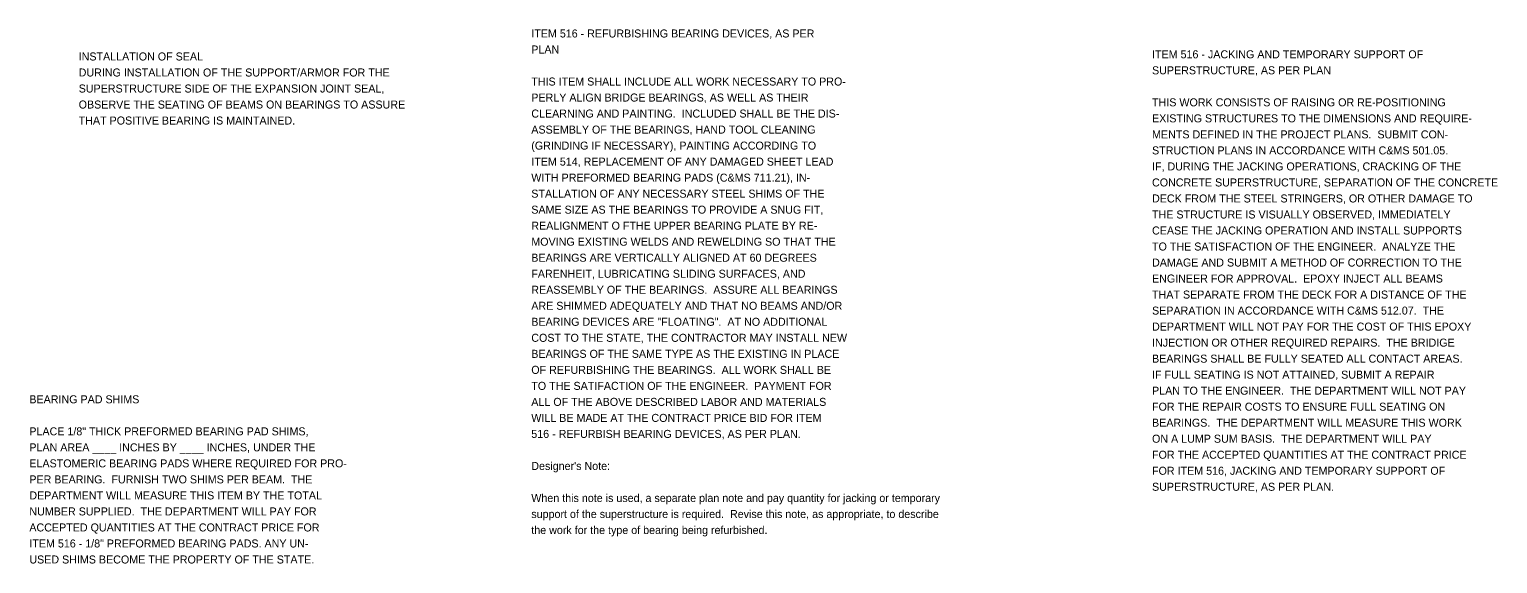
# Model space of a CAD drawing. Extents: x -11.4 to 50.8, y -16 to 31.7.
# Drawn here: x 25.08 to 50.76, y -14.14 to -4.8 of the extents above; entities that cross this region are included whole.
import ezdxf

# ---------------------------------------------------------------- set-up
doc = ezdxf.new("R2010")
doc.units = 0
doc.layers.add('SH_Text', color=7, linetype='Continuous')

msp = doc.modelspace()

# ---------------------------------------------------------------- texts
at = {"layer": 'SH_Text'}
for s, p in [('ITEM 516 - REFURBISHING BEARING DEVICES, AS PER', (33.857, -4.943)), ('PLAN', (33.857, -5.223)), ('INSTALLATION OF SEAL', (25.94, -5.345)), ('ITEM 516 - JACKING AND TEMPORARY SUPPORT OF', (44.715, -5.307)), ('DURING INSTALLATION OF THE SUPPORT/ARMOR FOR THE', (25.94, -5.625)), ('THIS ITEM SHALL INCLUDE ALL WORK NECESSARY TO PRO-', (33.857, -5.783)), ('SUPERSTRUCTURE, AS PER PLAN', (44.715, -5.587)), ('SUPERSTRUCTURE SIDE OF THE EXPANSION JOINT SEAL,', (25.94, -5.905)), ('OBSERVE THE SEATING OF BEAMS ON BEARINGS TO ASSURE', (25.94, -6.185)), ('PERLY ALIGN BRIDGE BEARINGS, AS WELL AS THEIR', (33.857, -6.063)), ('THIS WORK CONSISTS OF RAISING OR RE-POSITIONING', (44.715, -6.147)), ('THAT POSITIVE BEARING IS MAINTAINED.', (25.94, -6.465)), ('CLEARNING AND PAINTING.  INCLUDED SHALL BE THE DIS-', (33.857, -6.343)), ('EXISTING STRUCTURES TO THE DIMENSIONS AND REQUIRE-', (44.715, -6.427)), ('ASSEMBLY OF THE BEARINGS, HAND TOOL CLEANING', (33.857, -6.623)), ('MENTS DEFINED IN THE PROJECT PLANS.  SUBMIT CON-', (44.715, -6.707)), ('(GRINDING IF NECESSARY), PAINTING ACCORDING TO', (33.857, -6.903)), ('STRUCTION PLANS IN ACCORDANCE WITH C&MS 501.05.', (44.715, -6.987)), ('ITEM 514, REPLACEMENT OF ANY DAMAGED SHEET LEAD', (33.857, -7.183)), ('IF, DURING THE JACKING OPERATIONS, CRACKING OF THE', (44.715, -7.267)), ('WITH PREFORMED BEARING PADS (C&MS 711.21), IN-', (33.857, -7.463)), ('CONCRETE SUPERSTRUCTURE, SEPARATION OF THE CONCRETE', (44.715, -7.547)), ('STALLATION OF ANY NECESSARY STEEL SHIMS OF THE', (33.857, -7.743)), ('DECK FROM THE STEEL STRINGERS, OR OTHER DAMAGE TO', (44.715, -7.827)), ('SAME SIZE AS THE BEARINGS TO PROVIDE A SNUG FIT,', (33.857, -8.023)), ('REALIGNMENT O FTHE UPPER BEARING PLATE BY RE-', (33.857, -8.303)), ('THE STRUCTURE IS VISUALLY OBSERVED, IMMEDIATELY', (44.715, -8.107)), ('MOVING EXISTING WELDS AND REWELDING SO THAT THE', (33.857, -8.583)), ('CEASE THE JACKING OPERATION AND INSTALL SUPPORTS', (44.715, -8.387)), ('BEARINGS ARE VERTICALLY ALIGNED AT 60 DEGREES', (33.857, -8.863)), ('TO THE SATISFACTION OF THE ENGINEER.  ANALYZE THE', (44.715, -8.667)), ('DAMAGE AND SUBMIT A METHOD OF CORRECTION TO THE', (44.715, -8.947)), ('FARENHEIT, LUBRICATING SLIDING SURFACES, AND', (33.857, -9.143)), ('ENGINEER FOR APPROVAL.  EPOXY INJECT ALL BEAMS', (44.715, -9.227)), ('REASSEMBLY OF THE BEARINGS.  ASSURE ALL BEARINGS', (33.857, -9.423)), ('THAT SEPARATE FROM THE DECK FOR A DISTANCE OF THE', (44.715, -9.507)), ('ARE SHIMMED ADEQUATELY AND THAT NO BEAMS AND/OR', (33.857, -9.703)), ('SEPARATION IN ACCORDANCE WITH C&MS 512.07.  THE', (44.715, -9.787)), ('BEARING DEVICES ARE "FLOATING".  AT NO ADDITIONAL', (33.857, -9.983)), ('DEPARTMENT WILL NOT PAY FOR THE COST OF THIS EPOXY', (44.715, -10.067)), ('COST TO THE STATE, THE CONTRACTOR MAY INSTALL NEW', (33.857, -10.263)), ('INJECTION OR OTHER REQUIRED REPAIRS.  THE BRIDIGE', (44.715, -10.347)), ('BEARINGS OF THE SAME TYPE AS THE EXISTING IN PLACE', (33.857, -10.543)), ('BEARINGS SHALL BE FULLY SEATED ALL CONTACT AREAS.', (44.715, -10.627)), ('OF REFURBISHING THE BEARINGS.  ALL WORK SHALL BE', (33.857, -10.823)), ('IF FULL SEATING IS NOT ATTAINED, SUBMIT A REPAIR', (44.715, -10.907)), ('TO THE SATIFACTION OF THE ENGINEER.  PAYMENT FOR', (33.857, -11.103)), ('BEARING PAD SHIMS', (25.077, -11.338)), ('ALL OF THE ABOVE DESCRIBED LABOR AND MATERIALS', (33.857, -11.383)), ('PLAN TO THE ENGINEER.  THE DEPARTMENT WILL NOT PAY', (44.715, -11.187)), ('WILL BE MADE AT THE CONTRACT PRICE BID FOR ITEM', (33.857, -11.663)), ('FOR THE REPAIR COSTS TO ENSURE FULL SEATING ON', (44.715, -11.467)), ('PLACE 1/8" THICK PREFORMED BEARING PAD SHIMS,', (25.077, -11.898)), ('516 - REFURBISH BEARING DEVICES, AS PER PLAN.', (33.857, -11.943)), ('BEARINGS.  THE DEPARTMENT WILL MEASURE THIS WORK', (44.715, -11.747)), ('PLAN AREA ____ INCHES BY ____ INCHES, UNDER THE', (25.077, -12.178)), ('ON A LUMP SUM BASIS.  THE DEPARTMENT WILL PAY', (44.715, -12.027)), ('ELASTOMERIC BEARING PADS WHERE REQUIRED FOR PRO-', (25.077, -12.458)), ('FOR THE ACCEPTED QUANTITIES AT THE CONTRACT PRICE', (44.715, -12.307)), ("Designer's Note:", (33.857, -12.503)), ('FOR ITEM 516, JACKING AND TEMPORARY SUPPORT OF', (44.715, -12.587)), ('PER BEARING.  FURNISH TWO SHIMS PER BEAM.  THE', (25.077, -12.738)), ('SUPERSTRUCTURE, AS PER PLAN.', (44.715, -12.867)), ('DEPARTMENT WILL MEASURE THIS ITEM BY THE TOTAL', (25.077, -13.018)), ('When this note is used, a separate plan note and pay quantity for jacking or temporary', (33.857, -13.063)), ('NUMBER SUPPLIED.  THE DEPARTMENT WILL PAY FOR', (25.077, -13.298)), ('support of the superstructure is required.  Revise this note, as appropriate, to describe', (33.857, -13.343)), ('ACCEPTED QUANTITIES AT THE CONTRACT PRICE FOR', (25.077, -13.578)), ('the work for the type of bearing being refurbished.', (33.857, -13.623)), ('ITEM 516 - 1/8" PREFORMED BEARING PADS. ANY UN-', (25.077, -13.858)), ('USED SHIMS BECOME THE PROPERTY OF THE STATE.', (25.077, -14.138))]:
    msp.add_text(s, height=0.14, dxfattribs=at).set_placement(p)

doc.saveas('drawing.dxf')
